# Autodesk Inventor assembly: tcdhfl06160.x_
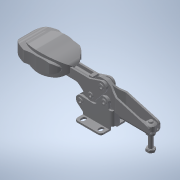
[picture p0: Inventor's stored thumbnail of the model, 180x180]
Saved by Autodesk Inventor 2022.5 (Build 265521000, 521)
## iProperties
Part Number: tcdhfl06160.x_
Material: 一般
Document SubType Name: Assembly
Designer: ImaoCorp
Sending System: SOLIDWORKS 2017-2017317
MC: AMD64
MC_MODEL: Intel64 Family 6 Model 60 Stepping 3, GenuineIntel
OS: Windows_NT
FRU: Parasolid Version 29.0, build 201,  4-17-2017
FORMAT: text
GUISE: transmit
KEY: tcdhfl06160
FILE: tcdhfl06160.x_t
DATE: Wed Sep 18 16:30:25 2019
Author: ImaoCorp
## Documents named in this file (8)
- X:\14_SW2022-Inv2022\00_全2023-1023新製品(TCC)まで\t\tcdhfl06160\TCDHFL06160.iam
- X:\14_SW2022-Inv2022\00_全2023-1023新製品(TCC)まで\t\tcdhfl06160\tcdhfl06160_01.ipt
- X:\14_SW2022-Inv2022\00_全2023-1023新製品(TCC)まで\t\tcdhfl06160\tcdhfl06160_02.ipt
- X:\14_SW2022-Inv2022\00_全2023-1023新製品(TCC)まで\t\tcdhfl06160\tcdhfl06160_03.ipt
- X:\14_SW2022-Inv2022\00_全2023-1023新製品(TCC)まで\t\tcdhfl06160\tcdhfl06160_04.ipt
- X:\14_SW2022-Inv2022\00_全2023-1023新製品(TCC)まで\t\tcdhfl06160\tcdhfl06160_05.ipt
- X:\14_SW2022-Inv2022\00_全2023-1023新製品(TCC)まで\t\tcdhfl06160\tcdhfl06160_06.ipt
- X:\14_SW2022-Inv2022\00_全2023-1023新製品(TCC)まで\t\tcdhfl06160\tcdhfl06160_07.ipt
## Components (7 placed, 7 different names)
1. tcdhfl06160_01
2. tcdhfl06160_02
3. tcdhfl06160_03
4. tcdhfl06160_04
5. tcdhfl06160_05
6. tcdhfl06160_06
7. tcdhfl06160_07
